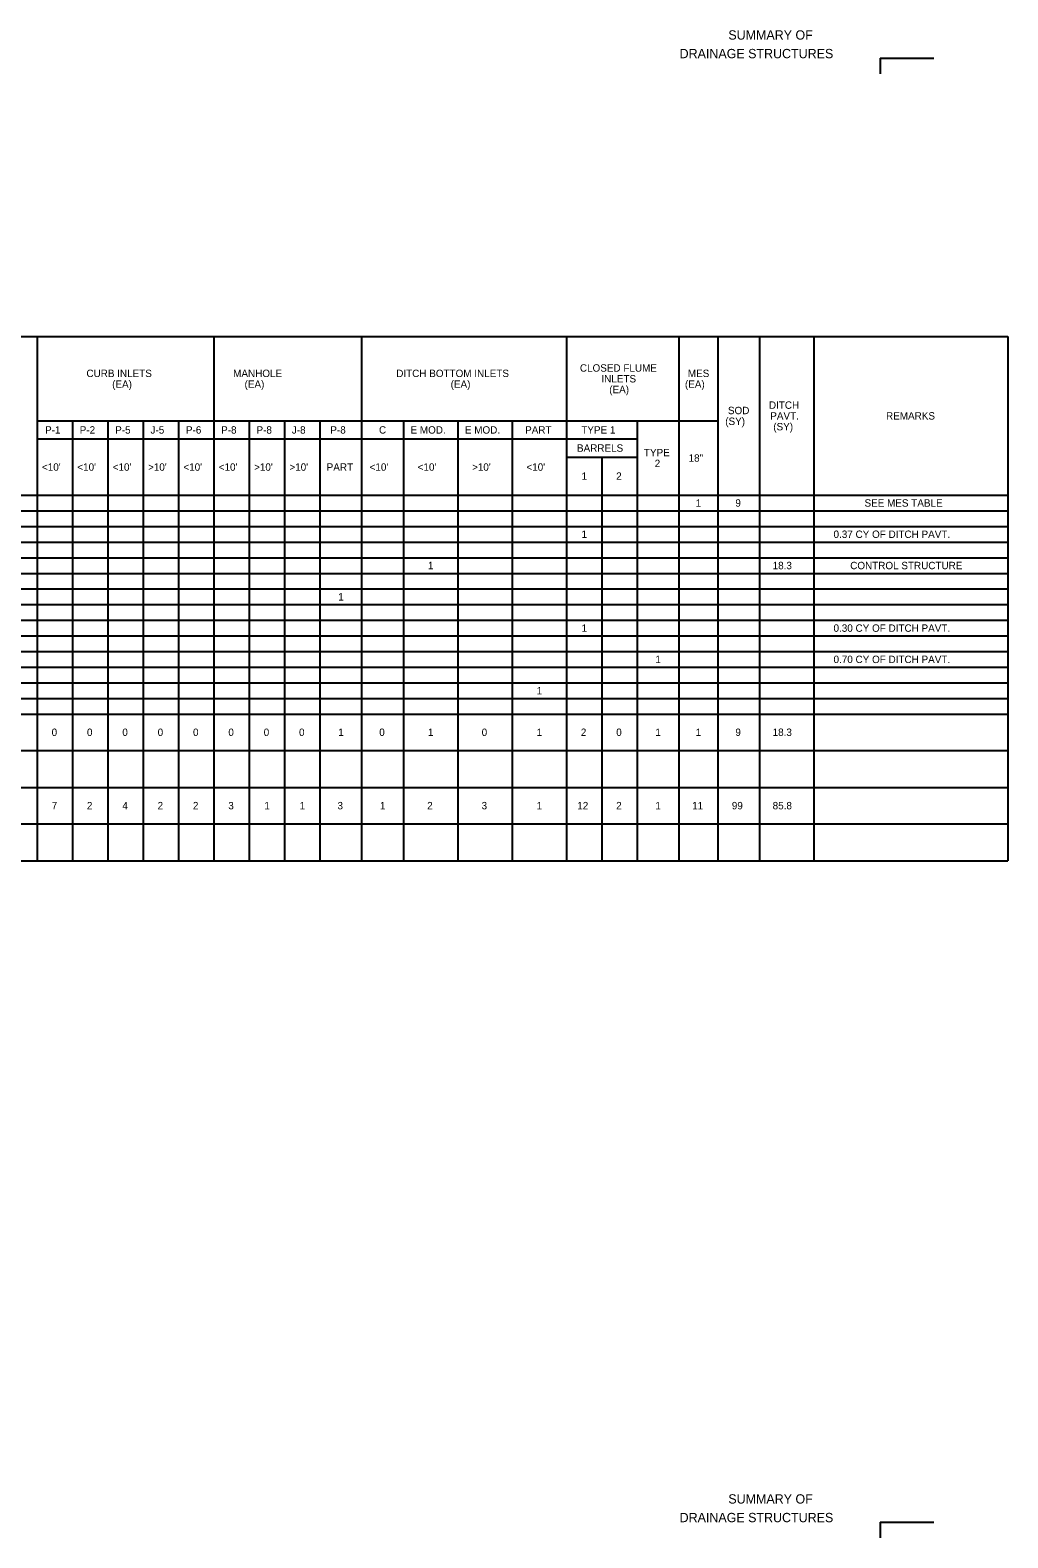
# Model space of a CAD drawing. Extents: x 0 to 765, y -1227 to 479.
# Drawn here: x 360 to 765, y -1227 to -602 of the extents above; entities that cross this region are included whole.
import ezdxf

# ---------------------------------------------------------------- set-up
doc = ezdxf.new("R2010")
doc.units = 0
for name, color, linetype in [('Default', 7, 'Continuous'), ('Miscellaneous0', 7, 'Continuous'), ('PlotBorder_dp', 7, 'Continuous'), ('SheetLines_dp', 7, 'Continuous'), ('TextMinor', 7, 'Continuous'), ('TextShtNo', 7, 'Continuous')]:
    doc.layers.add(name, color=color, linetype=linetype)

msp = doc.modelspace()

# ---------------------------------------------------------------- linework, layer by layer
at = {"layer": 'PlotBorder_dp'}
for p, q in [((362.91, -729.34), (362.91, -946.36)), ((362.91, -729.34), (362.91, -946.36)), ((436.04, -729.34), (436.04, -764.21)), ((497.16, -729.34), (497.16, -946.36)), ((497.16, -729.34), (497.16, -946.36)), ((581.91, -729.34), (581.91, -946.36)), ((581.91, -729.34), (581.91, -946.36)), ((628.41, -729.34), (628.41, -946.36)), ((628.41, -729.34), (628.41, -946.36)), ((644.54, -729.34), (644.54, -946.36)), ((644.54, -729.34), (644.54, -946.36)), ((661.79, -729.34), (661.79, -946.36)), ((661.79, -729.34), (661.79, -946.36)), ((684.29, -729.34), (684.29, -794.96)), ((684.29, -729.34), (684.29, -946.36)), ((362.91, -764.21), (644.54, -764.21)), ((362.91, -764.21), (644.54, -764.21)), ((377.54, -764.21), (377.54, -900.61)), ((377.54, -764.21), (377.54, -946.36)), ((392.16, -764.21), (392.16, -900.61)), ((392.16, -764.21), (392.16, -946.36)), ((406.79, -764.21), (406.79, -946.36)), ((421.41, -764.21), (421.41, -900.61)), ((421.41, -764.21), (421.41, -946.36)), ((436.04, -764.21), (436.04, -946.36)), ((450.66, -764.21), (450.66, -946.36)), ((450.66, -764.21), (450.66, -946.36)), ((465.29, -764.21), (465.29, -946.36)), ((465.29, -764.21), (465.29, -946.36)), ((479.91, -764.21), (479.91, -946.36)), ((479.91, -764.21), (479.91, -946.36)), ((514.41, -764.21), (514.41, -946.36)), ((514.41, -764.21), (514.41, -946.36)), ((536.91, -764.21), (536.91, -946.36)), ((536.91, -764.21), (536.91, -946.36)), ((559.41, -764.21), (559.41, -946.36)), ((559.41, -764.21), (559.41, -946.36)), ((611.16, -764.21), (611.16, -946.36)), ((611.16, -764.21), (611.16, -946.36)), ((362.91, -771.71), (559.41, -771.71)), ((362.91, -771.71), (611.16, -771.71)), ((406.79, -771.71), (406.79, -900.61)), ((436.04, -771.71), (436.04, -946.36)), ((581.91, -771.71), (611.16, -771.71)), ((581.91, -779.21), (611.16, -779.21)), ((581.91, -779.21), (611.16, -779.21)), ((596.54, -779.21), (596.54, -946.36)), ((596.54, -779.21), (596.54, -946.36)), ((0.29, -885.61), (764.54, -885.61)), ((684.29, -885.61), (684.29, -946.36)), ((85.04, -900.61), (764.54, -900.61)), ((85.04, -900.61), (764.54, -900.61)), ((0.29, -915.99), (764.54, -915.99)), ((377.54, -915.99), (377.54, -930.99)), ((392.16, -915.99), (392.16, -930.99)), ((406.79, -915.99), (406.79, -930.99)), ((421.41, -915.99), (421.41, -930.99)), ((85.04, -930.99), (764.54, -930.99)), ((85.04, -930.99), (764.54, -930.99))]:
    msp.add_line(p, q, dxfattribs=at)
at = {"layer": 'SheetLines_dp'}
for p, q in [((0.29, -729.34), (764.54, -729.34)), ((764.54, -729.34), (764.54, -946.36)), ((0.29, -794.96), (764.54, -794.96)), ((173.54, -794.96), (406.79, -794.96)), ((421.41, -794.96), (684.29, -794.96)), ((0.29, -915.99), (764.54, -915.99)), ((0.29, -946.36), (764.54, -946.36))]:
    msp.add_line(p, q, dxfattribs=at)
at = {"layer": 'TextMinor'}
for p, q in [((406.79, -794.96), (421.41, -794.96)), ((684.29, -794.96), (764.54, -794.96)), ((0.29, -801.44), (764.54, -801.44)), ((0.29, -801.44), (764.54, -801.44)), ((0.29, -807.91), (764.54, -807.91)), ((0.29, -807.91), (764.54, -807.91)), ((0.29, -814.39), (764.54, -814.39)), ((0.29, -814.39), (764.54, -814.39)), ((0.29, -820.86), (764.54, -820.86)), ((173.54, -820.86), (764.54, -820.86)), ((0.29, -827.34), (764.54, -827.34)), ((210.66, -827.34), (406.79, -827.34)), ((421.41, -827.34), (764.54, -827.34)), ((0.29, -833.81), (764.54, -833.81)), ((0.29, -833.81), (764.54, -833.81)), ((0.29, -840.29), (764.54, -840.29)), ((0.29, -840.29), (764.54, -840.29)), ((0.29, -846.76), (764.54, -846.76)), ((0.29, -846.76), (764.54, -846.76)), ((0.29, -853.24), (764.54, -853.24)), ((0.29, -853.24), (764.54, -853.24)), ((0.29, -859.71), (764.54, -859.71)), ((0.29, -859.71), (764.54, -859.71)), ((0.29, -866.19), (764.54, -866.19)), ((0.29, -866.19), (764.54, -866.19)), ((0.29, -872.66), (764.54, -872.66)), ((0.29, -872.66), (764.54, -872.66)), ((0.29, -879.14), (764.54, -879.14)), ((0.29, -879.14), (764.54, -879.14)), ((0.29, -885.61), (764.54, -885.61))]:
    msp.add_line(p, q, dxfattribs=at)
at = {"layer": 'TextShtNo'}
for p, q in [((711.76, -614.1), (733.9, -614.1)), ((711.76, -614.1), (711.76, -620.57)), ((711.76, -1220.13), (733.9, -1220.13)), ((711.76, -1220.13), (711.76, -1226.61))]:
    msp.add_line(p, q, dxfattribs=at)

# ---------------------------------------------------------------- texts
at = {"layer": 'Default'}
for s, height, p in [('SUMMARY OF', 3.855, (648.89, -606.39)), ('DRAINAGE STRUCTURES', 3.8546, (628.73, -614.1)), ('SUMMARY OF', 3.855, (648.89, -1212.42)), ('DRAINAGE STRUCTURES', 3.8546, (628.73, -1220.13))]:
    msp.add_text(s, height=height, dxfattribs=at).set_placement(p)
at = {"layer": 'Miscellaneous0'}
for s, height, p in [('CLOSED FLUME', 3.0625, (587.48, -743.85)), ('CURB INLETS', 3.0625, (383.28, -746.08)), ('(EA)', 3.062, (393.93, -750.54)), ('MANHOLE ', 3.062, (444, -746.08)), ('(EA)', 3.062, (448.72, -750.54)), ('DITCH BOTTOM INLETS', 3.0625, (511.48, -746.08)), ('(EA)', 3.062, (533.99, -750.54)), ('INLETS', 3.062, (596.38, -748.31)), ('(EA)', 3.062, (630.93, -750.54)), ('MES', 3.062, (632.14, -746.08)), ('(EA)', 3.062, (599.61, -752.77)), ('SOD', 3.062, (648.73, -761.45)), ('DITCH', 3.062, (665.69, -759.22)), ('PAVT.', 3.062, (666.24, -763.68)), ('REMARKS', 3.062, (714.15, -763.68)), ('P-1', 3.062, (366.18, -769.5)), ('P-2', 3.062, (380.51, -769.5)), ('P-5', 3.062, (395.18, -769.5)), ('J-5', 3.062, (409.8, -769.5)), ('P-6', 3.062, (424.45, -769.5)), ('P-8', 3.062, (439.02, -769.5)), ('P-8', 3.062, (453.65, -769.5)), ('J-8', 3.062, (468.27, -769.5)), ('P-8', 3.062, (484.21, -769.5)), ('C', 3.06, (504.35, -769.5)), ('E MOD.', 3.062, (517.38, -769.5)), ('E MOD.', 3.062, (539.88, -769.5)), ('PART', 3.062, (564.81, -769.5)), ('TYPE 1', 3.062, (588.05, -769.5)), ('(SY)', 3.062, (647.61, -765.91)), ('(SY)', 3.062, (667.49, -768.15)), ('BARRELS', 3.062, (586.27, -777)), ('TYPE', 3.062, (613.96, -778.89)), ('18"', 3.062, (632.44, -781.12)), ("<10'", 3.062, (364.9, -784.87)), ("<10'", 3.062, (379.52, -784.87)), ("<10'", 3.062, (394.15, -784.87)), (">10'", 3.062, (408.77, -784.87)), ("<10'", 3.062, (423.4, -784.87)), ("<10'", 3.062, (438.02, -784.87)), (">10'", 3.062, (452.65, -784.87)), (">10'", 3.062, (467.27, -784.87)), ('PART', 3.062, (482.69, -784.87)), ("<10'", 3.062, (500.46, -784.87)), ("<10'", 3.062, (520.34, -784.87)), (">10'", 3.062, (542.84, -784.87)), ("<10'", 3.062, (565.34, -784.87)), ('1', 3.06, (588.15, -788.62)), ('2', 3.06, (602.48, -788.62)), ('2', 3.06, (618.42, -783.35)), ('1', 3.06, (635.4, -799.73)), ('9', 3.06, (651.81, -799.73)), ('SEE MES TABLE', 3.0625, (705.24, -799.73)), ('1', 3.06, (588.15, -812.68)), ('0.37 CY OF DITCH PAVT.', 3.0625, (692.42, -812.68)), ('1', 3.06, (524.59, -825.63)), ('18.3', 3.062, (667.22, -825.63)), ('CONTROL STRUCTURE', 3.0625, (699.32, -825.63)), ('1', 3.06, (487.46, -838.58)), ('1', 3.06, (588.15, -851.53)), ('0.30 CY OF DITCH PAVT.', 3.0625, (692.42, -851.53)), ('1', 3.06, (618.71, -864.48)), ('0.70 CY OF DITCH PAVT.', 3.0625, (692.42, -864.48)), ('1', 3.06, (569.59, -877.43)), ('0', 3.06, (368.88, -894.65)), ('0', 3.06, (383.5, -894.65)), ('0', 3.06, (398.13, -894.65)), ('0', 3.06, (412.75, -894.65)), ('0', 3.06, (427.38, -894.65)), ('0', 3.06, (442, -894.65)), ('0', 3.06, (456.63, -894.65)), ('0', 3.06, (471.25, -894.65)), ('1', 3.06, (487.46, -894.65)), ('0', 3.06, (504.44, -894.65)), ('1', 3.06, (524.59, -894.65)), ('0', 3.06, (546.82, -894.65)), ('1', 3.06, (569.59, -894.65)), ('2', 3.06, (587.85, -894.65)), ('0', 3.06, (602.5, -894.65)), ('1', 3.06, (618.71, -894.65)), ('1', 3.06, (635.4, -894.65)), ('9', 3.06, (651.81, -894.65)), ('18.3', 3.062, (667.22, -894.65)), ('7', 3.06, (368.94, -925.02)), ('2', 3.06, (383.48, -925.02)), ('4', 3.06, (398.16, -925.02)), ('2', 3.06, (412.73, -925.02)), ('2', 3.06, (427.35, -925.02)), ('3', 3.06, (441.98, -925.02)), ('1', 3.06, (456.9, -925.02)), ('1', 3.06, (471.52, -925.02)), ('3', 3.06, (487.16, -925.02)), ('1', 3.06, (504.71, -925.02)), ('2', 3.06, (524.29, -925.02)), ('3', 3.06, (546.79, -925.02)), ('1', 3.06, (569.59, -925.02)), ('12', 3.062, (586.37, -925.02)), ('2', 3.06, (602.48, -925.02)), ('1', 3.06, (618.71, -925.02)), ('11', 3.062, (633.92, -925.02)), ('99', 3.062, (650.33, -925.02)), ('85.8', 3.062, (667.23, -925.02))]:
    msp.add_text(s, height=height, dxfattribs=at).set_placement(p)

doc.saveas('drawing.dxf')
